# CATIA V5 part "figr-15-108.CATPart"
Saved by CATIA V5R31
Part number: Part1
Bounding box of the stored display mesh (mm): x -60.955 to 60.955, y -33.748 to 33.748, z 0 to 6.052
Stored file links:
  D:\PROJECTS\Project 2021\US EDITION\CATIA V5 6R 2021\Resources\Part Files\c15_catia_v5_6r2021_prt\figr-15-108.CATPart
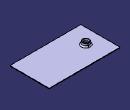
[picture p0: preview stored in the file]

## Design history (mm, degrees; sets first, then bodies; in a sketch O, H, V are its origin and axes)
SheetMetalParameters1: Thickness 1, BendRadius 5, KFactor 0.5 {= log(min(100,max(20*SheetMetalParameters1.BendRadius,SheetMetalParameters1.Thickness)/SheetMetalParameters1.Thickness))/log(100)/2}, ReliefRadialLength 1, ReliefAxialLength 2, MinimumBendRadius 0
Body1 (main body)
  Sketch1 on xy-plane, origin (0, 0, 0), H (1, 0, 0), V (0, 1, 0)
    line L1 (60.9549, 33.7477) -> (60.9549, -33.7477)
    line L2 (60.9549, -33.7477) -> (-60.9549, -33.7477)
    line L3 (-60.9549, -33.7477) -> (-60.9549, 33.7477)
    line L4 (-60.9549, 33.7477) -> (60.9549, 33.7477)
    vertical: L1 V, L3 V
    horizontal: L2 H, L4 H
    equidistance: L1 L3 O, L2 L4 O
  Wall1: Thickness 1, Profile Sketch1
  Sketch2 on face of Wall1, origin (0, 0, 1), H (1, 0, 0), V (0, 1, 0)
    point P1 (-35.8601, 0)
    coincidence: P1 H
  Sketch3 on face of Wall1, origin (-35.8601, 0, 1), H (1, 0, 0), V (0, 1, 0)
    point P1 (0, 0)
    reference projected point E1 (0, 0) from Sketch2.P1
    coincidence: E1 P1
  d_Stamp1: KFacteur 0.5 {= SheetMetalParameters1.KFactor}, Stamp_FilletRadius 2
